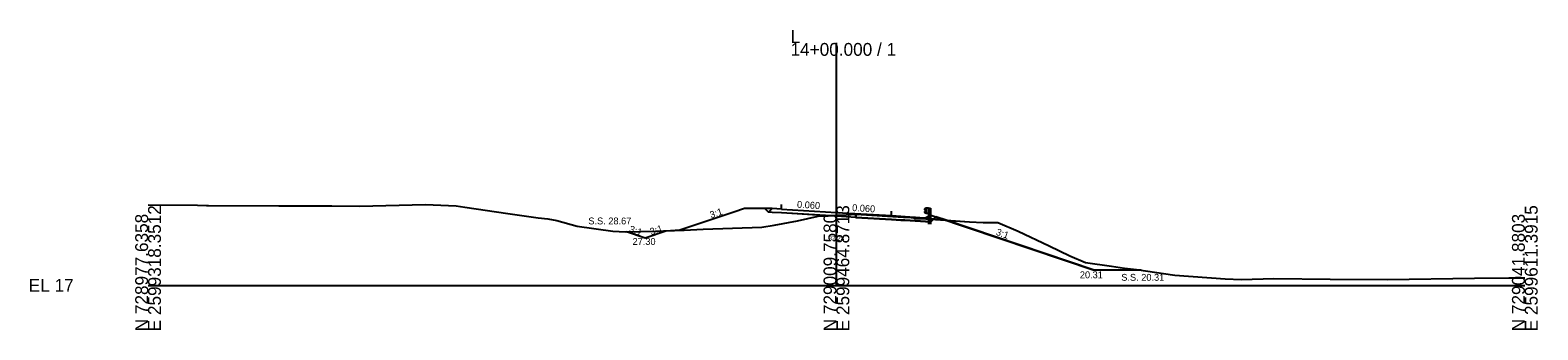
# Model space of a CAD drawing. Extents: x -26 to 3303, y -10 to 9555.
# Drawn here: x -25.7 to 302.8, y 7990.3 to 8055.7 of the extents above; entities that cross this region are included whole.
import ezdxf

# ---------------------------------------------------------------- set-up
doc = ezdxf.new("R2010")
doc.units = 0
for name, color, linetype in [('Exist Cross Section Cell', 7, 'Continuous'), ('Exist XS Center Line Elevation Label', 7, 'Continuous'), ('Exist XS Ground Line', 7, 'Continuous'), ('Prop XS Ditch Slope Text', 7, 'Continuous'), ('Prop XS Ditch Standard Text', 7, 'Continuous'), ('Prop XS Dump Level', 7, 'Continuous'), ('Prop XS Earthwork Shape', 7, 'Continuous'), ('Prop XS EOT Tick Mark', 7, 'Continuous'), ('Prop XS Finish Grade', 7, 'Continuous'), ('Prop XS Finish Grade Earthwork', 7, 'Continuous'), ('Prop XS Finish Grade Paved Shoulder', 7, 'Continuous'), ('Prop XS Finish Grade Pavement', 7, 'Continuous'), ('Prop XS Pvmt Edge Slope', 7, 'Continuous'), ('Prop XS SE Text', 7, 'Continuous'), ('Prop XS Side Slope Text', 7, 'Continuous'), ('Prop XS SS Elevation Text', 7, 'Continuous'), ('Prop XS Subgrade Earthwork', 7, 'Continuous'), ('Typical Curb CELL', 7, 'Continuous'), ('Typical Guardrail CELL', 7, 'Continuous')]:
    doc.layers.add(name, color=color, linetype=linetype)

msp = doc.modelspace()

# ---------------------------------------------------------------- linework, layer by layer
at = {"layer": 'Exist Cross Section Cell'}
for p, q in [((150, 8000), (150, 8052.86)), ((0, 8000), (150, 8000)), ((150, 8000), (300, 8000))]:
    msp.add_line(p, q, dxfattribs=at)
at = {"layer": 'Exist XS Ground Line'}
msp.add_lwpolyline([(0, 8017.56), (10.74, 8017.47), (12.74, 8017.45), (13.16, 8017.45), (28.48, 8017.34), (30.16, 8017.34), (31.84, 8017.35), (40.07, 8017.36), (46.06, 8017.28), (60.49, 8017.62), (67.14, 8017.34), (69.04, 8017.09), (78.42, 8015.71), (84.97, 8014.75), (87.11, 8014.49), (89.05, 8014.17), (93.47, 8012.93), (101.3, 8011.8), (104.03, 8011.67), (110.54, 8011.85), (116.81, 8012.08), (120.94, 8012.29), (133.71, 8012.69), (136.44, 8013.12), (141.55, 8014.07), (146.03, 8015.1), (150, 8015.28), (151.12, 8015.33), (154.22, 8015.5), (164.58, 8014.9), (166.29, 8014.82), (169.49, 8014.54), (179.01, 8013.84), (181.94, 8013.74), (185.17, 8013.69), (189.63, 8011.84), (196.35, 8008.64), (200.87, 8006.48), (204.3, 8005), (209.93, 8004.22), (212.77, 8003.76), (215.42, 8003.45), (223.74, 8002.22), (234.73, 8001.44), (238.26, 8001.27), (245.31, 8001.48), (257.61, 8001.39), (270.11, 8001.29), (289.06, 8001.55), (296.51, 8001.65), (300, 8001.66)], dxfattribs=at)
at = {"layer": 'Prop XS Dump Level'}
for p, q in [((138, 8016.65), (150, 8015.93)), ((150, 8015.93), (162, 8015.21))]:
    msp.add_line(p, q, dxfattribs=at)
at = {"layer": 'Prop XS Earthwork Shape'}
for points in [[(133.71, 8012.69), (136.44, 8013.12), (141.55, 8014.07), (146.03, 8015.1), (148.2, 8015.2), (138, 8015.81), (136, 8015.93), (135.21, 8015.98), (134.43, 8016.77), (130, 8016.77), (127.64, 8015.98), (115.84, 8012.05), (116.81, 8012.08), (120.94, 8012.29)], [(134.43, 8016.77), (130, 8016.77), (127.64, 8015.98), (115.84, 8012.05), (116.81, 8012.08), (120.94, 8012.29), (133.71, 8012.69), (136.44, 8013.12), (141.55, 8014.07), (146.03, 8015.1), (148.2, 8015.2), (138, 8015.81), (136, 8015.93), (135.21, 8015.98)], [(150, 8015.09), (148.2, 8015.2), (150, 8015.28), (151.12, 8015.33), (154.22, 8015.5), (154.22, 8014.84)], [(148.2, 8015.2), (150, 8015.28), (151.12, 8015.33), (154.22, 8015.5), (154.22, 8014.84), (150, 8015.09)], [(154.22, 8014.84), (162, 8014.37), (164, 8014.25), (164.89, 8014.2), (170.56, 8013.86), (171.13, 8014.42), (169.49, 8014.54), (166.29, 8014.82), (164.58, 8014.9), (154.22, 8015.5)], [(166.29, 8014.82), (169.49, 8014.54), (171.13, 8014.42), (170.56, 8013.86), (164.89, 8014.2), (164, 8014.25), (162, 8014.37), (154.22, 8014.84), (154.22, 8015.5), (164.58, 8014.9)], [(171.67, 8014.97), (173.88, 8014.22), (171.13, 8014.42)], [(171.13, 8014.42), (173.88, 8014.22), (171.67, 8014.97)], [(189.63, 8011.84), (196.35, 8008.64), (200.87, 8006.48), (204.3, 8005), (209.93, 8004.22), (212.77, 8003.76), (215.42, 8003.45), (216.37, 8003.31), (206.14, 8003.31), (173.88, 8014.22), (179.01, 8013.84), (181.94, 8013.74), (185.17, 8013.69)], [(179.01, 8013.84), (181.94, 8013.74), (185.17, 8013.69), (189.63, 8011.84), (196.35, 8008.64), (200.87, 8006.48), (204.3, 8005), (209.93, 8004.22), (212.77, 8003.76), (215.42, 8003.45), (216.37, 8003.31), (206.14, 8003.31), (173.88, 8014.22)], [(112.84, 8011.8), (108.35, 8010.3), (104.23, 8011.67), (110.54, 8011.85), (115.84, 8012.05)], [(112.84, 8011.8), (108.35, 8010.3), (104.23, 8011.67), (110.54, 8011.85), (115.84, 8012.05)]]:
    msp.add_lwpolyline(points, close=True, dxfattribs=at)
at = {"layer": 'Prop XS EOT Tick Mark'}
for p, q in [((138, 8016.65), (138, 8017.65)), ((162, 8015.21), (162, 8016.21))]:
    msp.add_line(p, q, dxfattribs=at)
at = {"layer": 'Prop XS Finish Grade'}
for p, q in [((136, 8016.77), (134.43, 8016.77)), ((170.03, 8015.09), (170.56, 8015.34)), ((170.56, 8015.34), (171.67, 8014.97))]:
    msp.add_line(p, q, dxfattribs=at)
at = {"layer": 'Prop XS Finish Grade Earthwork'}
for p, q in [((130, 8016.77), (127.64, 8015.98)), ((134.43, 8016.77), (130, 8016.77)), ((127.64, 8015.98), (115.84, 8012.05)), ((171.67, 8014.97), (206.14, 8003.31)), ((108.35, 8010.3), (104.23, 8011.67)), ((112.84, 8011.8), (108.35, 8010.3)), ((115.84, 8012.05), (112.84, 8011.8)), ((216.37, 8003.31), (206.14, 8003.31))]:
    msp.add_line(p, q, dxfattribs=at)
at = {"layer": 'Prop XS Finish Grade Paved Shoulder'}
for p, q in [((138, 8016.65), (136, 8016.77)), ((162, 8015.21), (167, 8014.91))]:
    msp.add_line(p, q, dxfattribs=at)
at = {"layer": 'Prop XS Finish Grade Pavement'}
for p, q in [((138, 8016.65), (150, 8015.93)), ((150, 8015.93), (162, 8015.21))]:
    msp.add_line(p, q, dxfattribs=at)
at = {"layer": 'Prop XS Pvmt Edge Slope'}
for p, q in [((135.21, 8015.98), (134.43, 8016.77)), ((136, 8016.77), (135.21, 8015.98)), ((170.01, 8014.41), (170.56, 8013.86)), ((170.56, 8013.86), (171.67, 8014.97))]:
    msp.add_line(p, q, dxfattribs=at)
at = {"layer": 'Prop XS Subgrade Earthwork'}
for p, q in [((135.21, 8015.98), (134.43, 8016.77)), ((136, 8015.93), (135.21, 8015.98)), ((138, 8015.81), (136, 8015.93)), ((150, 8015.09), (138, 8015.81)), ((154.22, 8014.84), (150, 8015.09)), ((154.22, 8014.84), (154.22, 8015.5)), ((154.22, 8014.84), (154.22, 8015.5)), ((154.22, 8014.84), (162, 8014.37)), ((162, 8014.37), (164, 8014.25)), ((164, 8014.25), (164.89, 8014.2)), ((164.89, 8014.2), (170.56, 8013.86)), ((170.56, 8013.86), (171.67, 8014.97))]:
    msp.add_line(p, q, dxfattribs=at)
at = {"layer": 'Typical Curb CELL'}
for p, q in [((166.99, 8014.49), (167, 8014.9)), ((170.01, 8014.41), (166.99, 8014.49)), ((167, 8014.91), (167, 8014.91)), ((167.01, 8014.91), (169.33, 8014.76)), ((167.23, 8014.64), (167.32, 8014.75)), ((167.35, 8014.64), (167.23, 8014.64)), ((167.32, 8014.75), (167.35, 8014.64)), ((167.99, 8014.57), (168.06, 8014.68)), ((168.16, 8014.6), (167.99, 8014.57)), ((168.06, 8014.68), (168.16, 8014.6)), ((168.48, 8014.6), (168.57, 8014.72)), ((168.6, 8014.61), (168.48, 8014.6)), ((168.57, 8014.72), (168.6, 8014.61)), ((169.24, 8014.53), (169.31, 8014.65)), ((169.41, 8014.57), (169.24, 8014.53)), ((169.31, 8014.65), (169.41, 8014.57)), ((169.33, 8014.76), (170.03, 8015.09)), ((169.83, 8014.76), (169.84, 8014.67)), ((169.98, 8014.71), (169.83, 8014.76)), ((169.84, 8014.67), (169.98, 8014.71)), ((170.01, 8014.41), (170.03, 8015.09))]:
    msp.add_line(p, q, dxfattribs=at)
for centre in [(167.09, 8014.73), (167.13, 8014.85), (167.49, 8014.77), (167.55, 8014.59), (167.6, 8014.55), (167.64, 8014.68), (167.71, 8014.67), (167.76, 8014.7), (167.81, 8014.59), (168, 8014.62), (168.21, 8014.6), (168.23, 8014.65), (168.24, 8014.71), (168.29, 8014.56), (168.39, 8014.61), (168.48, 8014.61), (168.6, 8014.56), (168.8, 8014.56), (168.85, 8014.52), (168.89, 8014.65), (169.01, 8014.67), (169.06, 8014.55), (169.25, 8014.59), (169.28, 8014.49), (169.46, 8014.57), (169.48, 8014.62), (169.73, 8014.58), (169.85, 8014.53), (169.95, 8014.8)]:
    msp.add_circle(centre, 0.00802, dxfattribs=at)
msp.add_arc((167.01, 8014.89), 0.0104, 86.5213, 178.5693, dxfattribs=at)
at = {"layer": 'Typical Guardrail CELL'}
for p, q in [((169.53, 8016.87), (169.24, 8016.67)), ((169.53, 8016.34), (169.24, 8016.54)), ((169.53, 8016.25), (169.24, 8016.04)), ((170.03, 8016.87), (169.53, 8016.87)), ((169.53, 8016.87), (169.53, 8015.71)), ((169.53, 8016.29), (169.53, 8016.34)), ((169.53, 8016.29), (169.53, 8016.25)), ((170.03, 8016.87), (170.03, 8014.39)), ((170.03, 8016.87), (170.53, 8016.87)), ((170.53, 8016.87), (170.53, 8014.39)), ((169.53, 8015.71), (169.24, 8015.92)), ((170.03, 8015.71), (169.53, 8015.71)), ((170.03, 8014.39), (170.53, 8014.39)), ((170.03, 8014.39), (170.03, 8013.38)), ((170.53, 8014.39), (170.53, 8013.38))]:
    msp.add_line(p, q, dxfattribs=at)
for centre, start, end in [((169.29, 8016.61), 125.003, 235.0112), ((169.29, 8015.98), 125.0059, 235.0366)]:
    msp.add_arc(centre, 0.0776, start, end, dxfattribs=at)

# ---------------------------------------------------------------- texts
at = {"layer": 'Exist Cross Section Cell'}
for s, p in [('L', (140, 8052.86)), ('14+00.000 / 1', (140, 8050.06)), ('EL 17', (-26, 7998.6))]:
    msp.add_text(s, height=2.8, dxfattribs=at).set_placement(p)
for s, p in [('E 2599318.3512', (2.8, 7990)), ('E 2599464.8713', (152.8, 7990)), ('E 2599611.3915', (302.8, 7990)), ('N 728977.6358', (0, 7990)), ('N 729009.7580', (150, 7990)), ('N 729041.8803', (300, 7990))]:
    msp.add_text(s, height=2.8, rotation=90, dxfattribs=at).set_placement(p)
at = {"layer": 'Exist XS Center Line Elevation Label'}
msp.add_text('32.28', height=1, dxfattribs=at).set_placement((148.26, 8009.78))
at = {"layer": 'Prop XS Ditch Slope Text'}
msp.add_text('3:1', height=1.5, rotation=340.5558, dxfattribs=at).set_placement((184.63, 8011.05))
at = {"layer": 'Prop XS Ditch Standard Text'}
msp.add_text('20.31', height=1.5, dxfattribs=at).set_placement((203.04, 8001.56))
at = {"layer": 'Prop XS Dump Level'}
for s, height, p in [('Case1', 0.04, (130, 8016.73)), ('Eop', 0.3, (154.22, 8015.2)), ('Eop', 0.3, (154.22, 8015.2)), ('Case1', 0.04, (170, 8014.57)), ('Case1', 0.04, (173, 8014.33))]:
    msp.add_text(s, height=height, dxfattribs=at).set_placement(p)
at = {"layer": 'Prop XS SE Text'}
for p in [(141.38, 8016.94), (153.38, 8016.22)]:
    msp.add_text('0.060', height=1.5, rotation=356.5664, dxfattribs=at).set_placement(p)
at = {"layer": 'Prop XS Side Slope Text'}
for rotation, p in [(18.4349, (122.69, 8014.61)), (341.0185, (104.7, 8011.69)), (18.4349, (109.64, 8010.94))]:
    msp.add_text('3:1', height=1.5, rotation=rotation, dxfattribs=at).set_placement(p)
at = {"layer": 'Prop XS SS Elevation Text'}
for s, p in [('S.S. 28.67', (95.94, 8013.3)), ('27.30', (105.57, 8008.83)), ('S.S. 20.31', (212.07, 8001.01))]:
    msp.add_text(s, height=1.5, dxfattribs=at).set_placement(p)

doc.saveas('drawing.dxf')
